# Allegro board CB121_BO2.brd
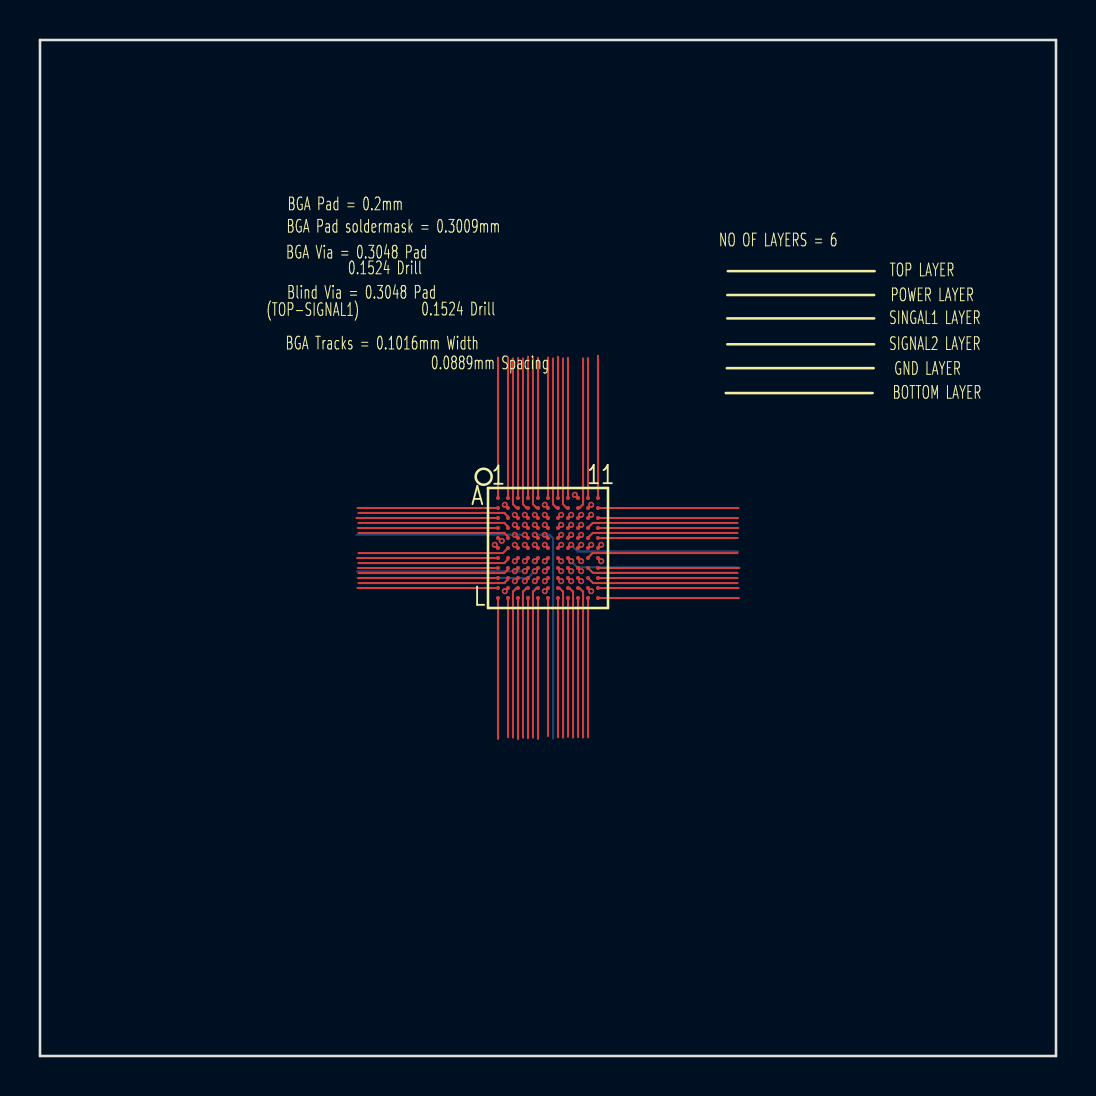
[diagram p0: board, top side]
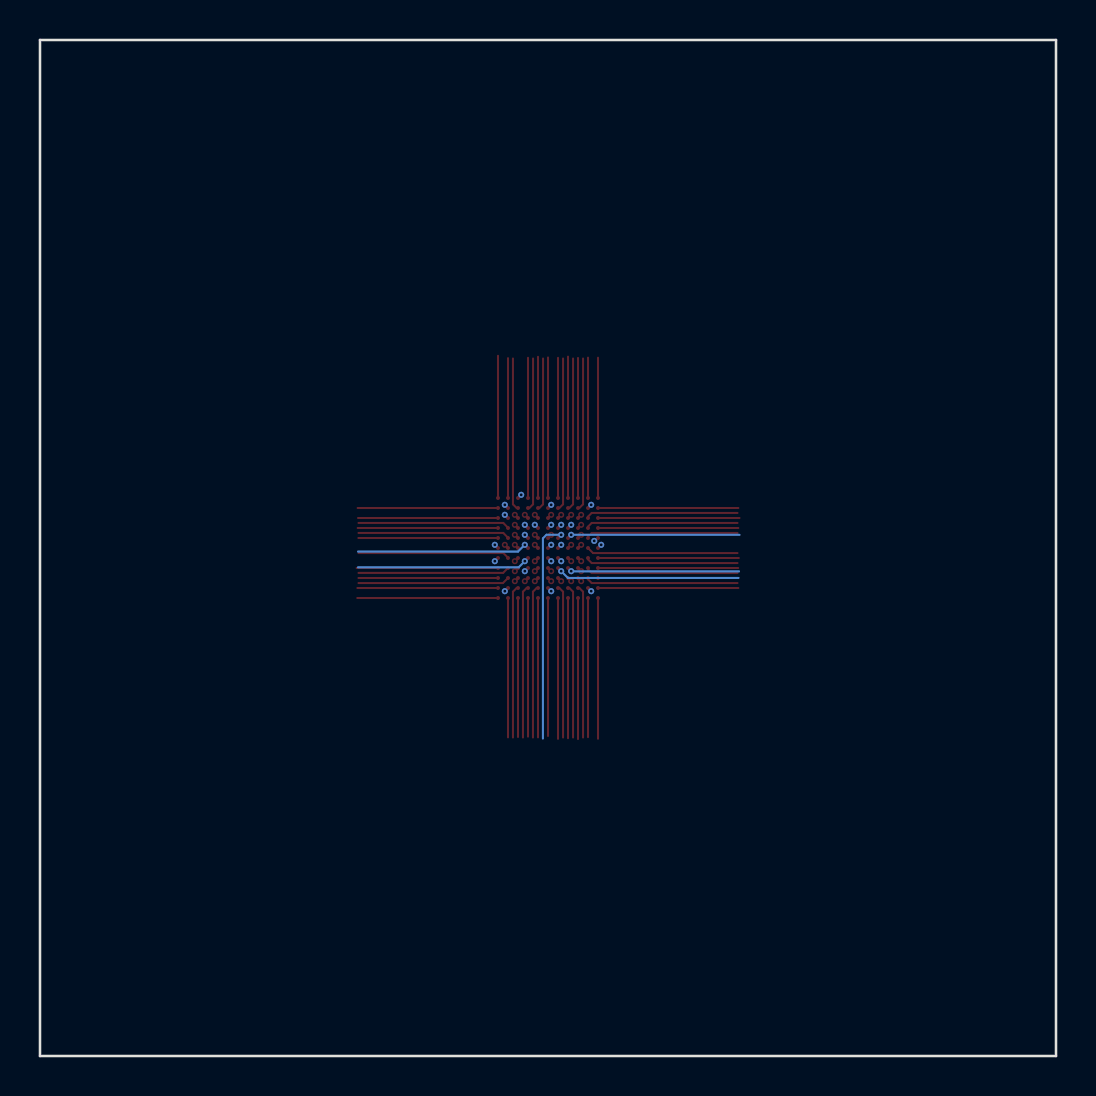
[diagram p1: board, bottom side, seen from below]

Outline 50.8 x 50.8 mm; copper layers: TOP, POWER, SIGNAL1, SIGNAL2, GND, BOTTOM. Coordinates in mm from the lower left corner of the outline.
Outline path: 0,50.8 0,0 50.8,0 50.8,50.8 0,50.8

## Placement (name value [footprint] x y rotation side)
U1  -  [BGA11X11-121_0-2MM]  25.4 25.4 0 top

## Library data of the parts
U1 = BGA11X11-121_0-2MM

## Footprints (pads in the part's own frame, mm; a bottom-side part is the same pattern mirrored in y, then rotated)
BGA11X11-121_0-2MM
  round 0.2 smd: A1(-2.5,2.5) A2(-2,2.5) A3(-1.5,2.5) A4(-1,2.5) A5(-0.5,2.5) A6(0,2.5) A7(0.5,2.5) A8(1,2.5) A9(1.5,2.5) A10(2,2.5) A11(2.5,2.5) B1(-2.5,2) B2(-2,2) B3(-1.5,2) B4(-1,2) B5(-0.5,2) B6(0,2) B7(0.5,2) B8(1,2) B9(1.5,2) B10(2,2) B11(2.5,2) C1(-2.5,1.5) C2(-2,1.5) C3(-1.5,1.5) C4(-1,1.5) C5(-0.5,1.5) C6(0,1.5) C7(0.5,1.5) C8(1,1.5) C9(1.5,1.5) C10(2,1.5) C11(2.5,1.5) D1(-2.5,1) D2(-2,1) D3(-1.5,1) D4(-1,1) D5(-0.5,1) D6(0,1) D7(0.5,1) D8(1,1) D9(1.5,1) D10(2,1) D11(2.5,1) E1(-2.5,0.5) E2(-2,0.5) E3(-1.5,0.5) E4(-1,0.5) E5(-0.5,0.5) E6(0,0.5) E7(0.5,0.5) E8(1,0.5) E9(1.5,0.5) E10(2,0.5) E11(2.5,0.5) F1(-2.5,0) F2(-2,0) F3(-1.5,0) F4(-1,0) F5(-0.5,0) F6(0,0) F7(0.5,0) F8(1,0) F9(1.5,0) F10(2,0) F11(2.5,0) G1(-2.5,-0.5) G2(-2,-0.5) G3(-1.5,-0.5) G4(-1,-0.5) G5(-0.5,-0.5) G6(0,-0.5) G7(0.5,-0.5) G8(1,-0.5) G9(1.5,-0.5) G10(2,-0.5) G11(2.5,-0.5) H1(-2.5,-1) H2(-2,-1) H3(-1.5,-1) H4(-1,-1) H5(-0.5,-1) H6(0,-1) H7(0.5,-1) H8(1,-1) H9(1.5,-1) H10(2,-1) H11(2.5,-1) J1(-2.5,-1.5) J2(-2,-1.5) J3(-1.5,-1.5) J4(-1,-1.5) J5(-0.5,-1.5) J6(0,-1.5) J7(0.5,-1.5) J8(1,-1.5) J9(1.5,-1.5) J10(2,-1.5) J11(2.5,-1.5) K1(-2.5,-2) K2(-2,-2) K3(-1.5,-2) K4(-1,-2) K5(-0.5,-2) K6(0,-2) K7(0.5,-2) K8(1,-2) K9(1.5,-2) K10(2,-2) K11(2.5,-2) L1(-2.5,-2.5) L2(-2,-2.5) L3(-1.5,-2.5) L4(-1,-2.5) L5(-0.5,-2.5) L6(0,-2.5) L7(0.5,-2.5) L8(1,-2.5) L9(1.5,-2.5) L10(2,-2.5) L11(2.5,-2.5)

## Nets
GND: U1.B2 U1.B10 U1.E1 U1.F5 U1.F6 U1.G5 U1.G6 U1.G11 U1.K2 U1.K10
VCC: U1.B6 U1.F1 U1.F11 U1.K6
A1: U1.A1
A2: U1.A2
A3: U1.A3
A4: U1.A4
A5: U1.A5
A6: U1.A6
A7: U1.A7
A8: U1.A8
A10: U1.A10
A11: U1.A11
B1: U1.B1
B3: U1.B3
B4: U1.B4
B5: U1.B5
B7: U1.B7
B8: U1.B8
B9: U1.B9
B11: U1.B11
C1: U1.C1
C2: U1.C2
C3: U1.C3
C4: U1.C4
C5: U1.C5
C6: U1.C6
C7: U1.C7
C8: U1.C8
C9: U1.C9
C11: U1.C11
D1: U1.D1
D2: U1.D2
D3: U1.D3
D4: U1.D4
D5: U1.D5
D6: U1.D6
D7: U1.D7
D8: U1.D8
D9: U1.D9
D10: U1.D10
D11: U1.D11
E2: U1.E2
E3: U1.E3
E4: U1.E4
E5: U1.E5
E6: U1.E6
E7: U1.E7
E8: U1.E8
E9: U1.E9
E10: U1.E10
E11: U1.E11
F2: U1.F2
F3: U1.F3
F4: U1.F4
F7: U1.F7
F8: U1.F8
F9: U1.F9
F10: U1.F10
G1: U1.G1
G2: U1.G2
G3: U1.G3
G4: U1.G4
G7: U1.G7
G8: U1.G8
G9: U1.G9
G10: U1.G10
H1: U1.H1
H2: U1.H2
H3: U1.H3
H4: U1.H4
H5: U1.H5
H6: U1.H6
H7: U1.H7
H8: U1.H8
H9: U1.H9
H10: U1.H10
H11: U1.H11
J1: U1.J1
J2: U1.J2
J3: U1.J3
J4: U1.J4
J5: U1.J5
J6: U1.J6
J7: U1.J7
J8: U1.J8
J9: U1.J9
J10: U1.J10
J11: U1.J11
K1: U1.K1
K3: U1.K3
K4: U1.K4
K5: U1.K5
K7: U1.K7
K8: U1.K8
K9: U1.K9
K11: U1.K11
L1: U1.L1
L2: U1.L2
L3: U1.L3
L4: U1.L4
L5: U1.L5
L6: U1.L6
L7: U1.L7
L8: U1.L8
L9: U1.L9
L10: U1.L10
L11: U1.L11
VPP_2V5: U1.C10
VPP_FAST: U1.A9

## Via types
v1: diameter 0.305, hole 0.152, TOP to SIGNAL1, 33 vias
v2: diameter 0.305, hole 0.152, TOP to BOTTOM, 29 vias

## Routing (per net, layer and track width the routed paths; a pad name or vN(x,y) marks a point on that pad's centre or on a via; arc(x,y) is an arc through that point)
GND: length 2.3
  TOP w0.102: v2(25.24,25.56) U1.F6 ; v2(27.56,23.24) U1.K10 ; U1.E1 23.04,25.76 v2(23.09,25.76) ; v2(24.74,24.74) U1.G5 ; v2(25.24,24.74) U1.G6 ; v2(23.24,23.24) U1.K2 ; v2(28.06,24.74) U1.G11 ; v2(23.24,27.56) U1.B2 ; v2(27.56,27.56) U1.B10 ; v2(24.74,25.56) U1.F5
VCC: length 0.9
  TOP w0.102: v2(28.06,25.56) U1.F11 ; v2(25.24,23.24) U1.K6 ; v2(22.74,25.56) U1.F1 ; v2(25.24,27.56) U1.B6
A1: length 7
  TOP w0.102: U1.A1 22.9,34.91
A2: length 7
  TOP w0.102: U1.A2 23.4,34.92
A3: length 7
  TOP w0.102: U1.A3 23.9,34.9
A4: length 7.1
  TOP w0.102: U1.A4 24.4,34.97
A5: length 7
  TOP w0.102: U1.A5 24.9,34.91
A6: length 7
  TOP w0.102: U1.A6 25.4,34.92
A7: length 7.1
  TOP w0.102: U1.A7 25.9,34.96
A8: length 7
  TOP w0.102: U1.A8 26.4,34.91
A10: length 7
  TOP w0.102: U1.A10 27.4,34.89
A11: length 7.1
  TOP w0.102: U1.A11 27.9,35.01
B1: length 7
  TOP w0.102: U1.B1 15.88,27.4
B3: length 7.6
  TOP w0.102: 23.65,34.87 23.65,27.58 23.83,27.4 U1.B3
B4: length 7.6
  TOP w0.102: U1.B4 24.33,27.4 24.15,27.58 24.15,34.87
B5: length 7.6
  TOP w0.102: U1.B5 24.83,27.4 24.65,27.58 24.65,34.87
B7: length 7.6
  TOP w0.102: U1.B7 25.83,27.4 25.65,27.58 25.65,34.87
B8: length 7.6
  TOP w0.102: U1.B8 26.33,27.4 26.15,27.58 26.15,34.87
B9: length 7.6
  TOP w0.102: 27.15,34.87 27.15,27.58 26.97,27.4 U1.B9
B11: length 7
  TOP w0.102: U1.B11 34.92,27.4
C1: length 7.1
  TOP w0.102: U1.C1 15.83,26.9
C2: length 7.6
  TOP w0.102: U1.C2 23.4,26.97 23.22,27.15 15.93,27.15
C3: length 8.1
  TOP w0.102: v1(23.74,27.06) U1.C3
  SIGNAL1 w0.102: v1(23.74,27.06) 23.74,34.92
C4: length 8
  TOP w0.102: v1(24.24,27.06) U1.C4
  SIGNAL1 w0.102: v1(24.24,27.06) 24.24,34.88
C5: length 8.1
  TOP w0.102: v1(24.74,27.06) U1.C5
  SIGNAL1 w0.102: v1(24.74,27.06) 24.74,34.92
C6: length 8.2
  TOP w0.102: v1(25.24,27.06) U1.C6
  SIGNAL1 w0.102: 24.94,34.92 24.94,27.36 v1(25.24,27.06)
C7: length 8.1
  TOP w0.102: v1(26.06,27.06) U1.C7
  SIGNAL1 w0.102: v1(26.06,27.06) 26.06,34.92
C8: length 8.2
  TOP w0.102: v1(26.56,27.06) U1.C8
  SIGNAL1 w0.102: v1(26.56,27.06) 26.39,27.23 26.39,34.92
C9: length 8.1
  TOP w0.102: v1(27.06,27.06) U1.C9
  SIGNAL1 w0.102: v1(27.06,27.06) 27.06,34.92
C11: length 7
  TOP w0.102: U1.C11 34.9,26.9
D1: length 7
  TOP w0.102: U1.D1 15.88,26.4
D2: length 7.6
  TOP w0.102: 15.93,26.65 23.22,26.65 23.4,26.47 U1.D2
D3: length 8.2
  TOP w0.102: v1(23.74,26.56) U1.D3
  SIGNAL1 w0.102: 15.88,26.9 23.4,26.9 v1(23.74,26.56)
D4: length 8.6
  TOP w0.102: v2(24.24,26.56) U1.D4
  SIGNAL2 w0.102: v2(24.24,26.56) 24.24,34.92
D5: length 8.6
  TOP w0.102: v2(24.74,26.56) U1.D5
  SIGNAL2 w0.102: v2(24.74,26.56) 24.74,34.93
D6: length 8.7
  TOP w0.102: v2(25.24,26.56) U1.D6
  SIGNAL2 w0.102: v2(25.24,26.56) 25.55,26.87 25.55,34.94
D7: length 8.8
  TOP w0.102: v2(26.06,26.56) U1.D7
  SIGNAL2 w0.102: 25.76,34.92 25.76,26.75 25.94,26.56 v2(26.06,26.56)
D8: length 8.6
  TOP w0.102: v2(26.56,26.56) U1.D8
  SIGNAL2 w0.102: v2(26.56,26.56) 34.93,26.56
D9: length 8.1
  TOP w0.102: v1(27.06,26.56) U1.D9
  SIGNAL1 w0.102: v1(27.06,26.56) 34.92,26.56
D10: length 7.6
  TOP w0.102: U1.D10 27.4,26.42 27.64,26.65 34.87,26.65
D11: length 7
  TOP w0.102: U1.D11 34.92,26.4
E2: length 7.6
  TOP w0.102: 15.93,26.15 23.22,26.15 23.4,25.97 U1.E2
E3: length 8.3
  TOP w0.102: v1(23.74,26.06) U1.E3
  SIGNAL1 w0.102: 15.88,26.59 23.21,26.59 v1(23.74,26.06)
E4: length 8.6
  TOP w0.102: v2(24.24,26.06) U1.E4
  BOTTOM w0.102: v2(24.24,26.06) 15.83,26.06
E5: length 11.2
  TOP w0.102: v2(24.74,26.06) U1.E5
  BOTTOM w0.102: v2(24.74,26.06) 25.48,26.06 25.65,25.88 25.65,15.87
E6: length 9.3
  TOP w0.102: v1(25.24,26.06) U1.E6
  SIGNAL1 w0.102: v1(25.24,26.06) 25.37,26.06 25.55,26.24 25.55,34.9
E7: length 9.2
  TOP w0.102: v1(26.06,26.06) U1.E7
  SIGNAL1 w0.102: v1(26.06,26.06) 25.96,26.06 25.76,26.26 25.76,34.9
E8: length 8.6
  TOP w0.102: v2(26.56,26.06) U1.E8
  SIGNAL2 w0.102: v2(26.56,26.06) 34.9,26.06
E9: length 8.2
  TOP w0.102: v1(27.06,26.06) U1.E9
  SIGNAL1 w0.102: v1(27.06,26.06) 27.34,26.34 34.92,26.34
E10: length 7.6
  TOP w0.102: U1.E10 27.4,25.92 27.64,26.15 34.87,26.15
E11: length 7
  TOP w0.102: U1.E11 34.88,25.9
F2: length 7.6
  TOP w0.102: U1.F2 23.15,25.15 15.93,25.15
F3: length 8.4
  TOP w0.102: v1(23.74,25.56) U1.F3
  SIGNAL1 w0.102: v1(23.74,25.56) 23.04,26.26 15.88,26.26
F4: length 8.7
  TOP w0.102: v1(24.24,25.56) U1.F4
  SIGNAL1 w0.102: 15.9,25.25 23.95,25.25 24.24,25.54 v1(24.24,25.56)
F7: length 9.2
  TOP w0.102: v1(26.06,25.56) U1.F7
  SIGNAL1 w0.102: v1(26.06,25.56) 26.06,25.48 26.29,25.25 34.9,25.25
F8: length 8.7
  TOP w0.102: v2(26.56,25.56) U1.F8
  BOTTOM w0.102: v2(26.56,25.56) 26.56,25.56 26.9,25.22 34.9,25.22
F9: length 8.3
  TOP w0.102: v1(27.06,25.56) U1.F9
  SIGNAL1 w0.102: v1(27.06,25.56) 27.64,26.14 34.92,26.14
F10: length 7.7
  TOP w0.102: v1(27.56,25.56) U1.F10
  SIGNAL1 w0.102: 34.92,25.88 27.88,25.88 v1(27.56,25.56)
G1: length 7
  TOP w0.102: U1.G1 15.86,24.9
G2: length 7.6
  TOP w0.102: U1.G2 23.4,24.83 23.22,24.65 15.93,24.65
G3: length 8.1
  TOP w0.102: v1(23.74,24.74) U1.G3
  SIGNAL1 w0.102: v1(23.74,24.74) 15.88,24.74
G4: length 8.7
  TOP w0.102: v1(24.24,24.74) U1.G4
  SIGNAL1 w0.102: v1(24.24,24.74) 24.2,24.74 23.9,25.04 15.87,25.04
G7: length 9.2
  TOP w0.102: v1(26.06,24.74) U1.G7
  SIGNAL1 w0.102: 34.87,25.04 26.34,25.04 26.06,24.76 v1(26.06,24.74)
G8: length 8.7
  TOP w0.102: v2(26.56,24.74) U1.G8
  BOTTOM w0.102: v2(26.56,24.74) 26.87,24.43 34.9,24.43
G9: length 8.2
  TOP w0.102: v1(27.06,24.74) U1.G9
  SIGNAL1 w0.102: 34.92,24.43 27.37,24.43 v1(27.06,24.74)
G10: length 7.6
  TOP w0.102: U1.G10 27.4,24.92 27.63,25.15 34.87,25.15
H1: length 7
  TOP w0.102: U1.H1 15.89,24.4
H2: length 7.6
  TOP w0.102: U1.H2 23.4,24.33 23.22,24.15 15.93,24.15
H3: length 8.1
  TOP w0.102: v1(23.74,24.24) U1.H3
  SIGNAL1 w0.102: v1(23.74,24.24) 15.88,24.24
H4: length 8.8
  TOP w0.102: v2(24.24,24.24) U1.H4
  BOTTOM w0.102: v2(24.24,24.24) 24.32,24.24 24.31,24.23 15.85,24.23
H5: length 9.2
  TOP w0.102: v2(24.74,24.24) U1.H5
  BOTTOM w0.102: 15.87,23.9 24.4,23.9 v2(24.74,24.24)
H6: length 8.7
  TOP w0.102: v1(25.24,24.24) U1.H6
  SIGNAL1 w0.102: 25.55,15.93 25.55,23.9 25.24,24.21 v1(25.24,24.24)
H7: length 8.7
  TOP w0.102: v1(26.06,24.24) U1.H7
  SIGNAL1 w0.102: v1(26.06,24.24) 26.04,24.24 25.76,23.95 25.76,15.93
H8: length 8.5
  TOP w0.102: v2(26.56,24.24) U1.H8
  SIGNAL2 w0.102: v2(26.56,24.24) 34.88,24.24
H9: length 8.1
  TOP w0.102: v1(27.06,24.24) U1.H9
  SIGNAL1 w0.102: v1(27.06,24.24) 34.92,24.24
H10: length 7.6
  TOP w0.102: U1.H10 27.64,24.16 34.87,24.16
H11: length 7.1
  TOP w0.102: U1.H11 34.97,24.4
J1: length 7
  TOP w0.102: U1.J1 15.92,23.9
J2: length 7.6
  TOP w0.102: 15.93,23.65 23.22,23.65 23.4,23.83 U1.J2
J3: length 8.1
  TOP w0.102: v1(23.74,23.74) U1.J3
  SIGNAL1 w0.102: v1(23.74,23.74) 23.74,15.88
J4: length 8.1
  TOP w0.102: v1(24.24,23.74) U1.J4
  SIGNAL1 w0.102: v1(24.24,23.74) 24.24,15.88
J5: length 8.1
  TOP w0.102: v1(24.74,23.74) U1.J5
  SIGNAL1 w0.102: v1(24.74,23.74) 24.74,15.88
J6: length 8.2
  TOP w0.102: v1(25.24,23.74) U1.J6
  SIGNAL1 w0.102: v1(25.24,23.74) 24.94,23.44 24.94,15.88
J7: length 8.1
  TOP w0.102: v1(26.06,23.74) U1.J7
  SIGNAL1 w0.102: v1(26.06,23.74) 26.06,15.88
J8: length 8.1
  TOP w0.102: v1(26.56,23.74) U1.J8
  SIGNAL1 w0.102: v1(26.56,23.74) 26.56,15.88
J9: length 8.1
  TOP w0.102: v1(27.06,23.74) U1.J9
  SIGNAL1 w0.102: v1(27.06,23.74) 34.92,23.74
J10: length 7.6
  TOP w0.102: U1.J10 27.65,23.65 34.87,23.65
J11: length 7
  TOP w0.102: U1.J11 34.88,23.9
K1: length 7
  TOP w0.102: U1.K1 15.88,23.4
K3: length 7.6
  TOP w0.102: 23.65,15.93 23.65,23.22 23.83,23.4 U1.K3
K4: length 7.6
  TOP w0.102: 24.15,15.93 24.15,23.22 24.33,23.4 U1.K4
K5: length 7.6
  TOP w0.102: 24.65,15.93 24.65,23.22 24.83,23.4 U1.K5
K7: length 7.6
  TOP w0.102: U1.K7 25.97,23.4 26.15,23.22 26.15,15.93
K8: length 7.6
  TOP w0.102: U1.K8 26.47,23.4 26.65,23.22 26.65,15.93
K9: length 7.6
  TOP w0.102: 27.15,15.93 27.15,23.22 26.97,23.4 U1.K9
K11: length 7
  TOP w0.102: U1.K11 34.93,23.4
L1: length 7
  TOP w0.102: U1.L1 22.9,15.86
L2: length 7
  TOP w0.102: U1.L2 23.4,15.94
L3: length 7.1
  TOP w0.102: U1.L3 23.9,15.85
L4: length 7
  TOP w0.102: U1.L4 24.4,15.89
L5: length 7
  TOP w0.102: U1.L5 24.9,15.86
L6: length 6.9
  TOP w0.102: U1.L6 25.4,16
L7: length 7
  TOP w0.102: U1.L7 25.9,15.93
L8: length 6.9
  TOP w0.102: U1.L8 26.4,15.97
L9: length 6.9
  TOP w0.102: U1.L9 26.9,15.95
L10: length 7
  TOP w0.102: U1.L10 27.4,15.93
L11: length 7
  TOP w0.102: U1.L11 34.94,22.9
VPP_2V5: length 0.2
  TOP w0.102: v2(27.56,27.06) U1.C10
VPP_FAST: length 0.2
  TOP w0.102: v2(26.74,28.06) U1.A9

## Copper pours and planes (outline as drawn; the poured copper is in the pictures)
GND on GND: 22.38,28.45 28.42,28.45 28.45,28.42 28.45,22.38 28.42,22.35 22.38,22.35 22.35,22.38 22.35,28.42
VCC on POWER: 22.38,28.45 25.65,28.45 25.65,25.86 25.73,25.78 28.45,25.78 28.45,22.38 28.42,22.35 22.38,22.35 22.35,22.38 22.35,28.42
VPP_2V5 on POWER: 25.73,27.53 28.35,27.53 28.45,27.43 28.45,25.91 25.81,25.91 25.73,25.98
VPP_FAST on POWER: 25.76,28.45 28.37,28.45 28.42,28.4 28.42,27.61 25.76,27.61

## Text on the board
Ref Des/Silkscreen Top: (TOP-SIGNAL1) | BGA Tracks = 0.1016mm Width | BGA Via = 0.3048 Pad | 0.1524 Drill | BGA Pad soldermask = 0.3009mm | Blind Via = 0.3048 Pad | BGA Pad = 0.2mm | 0.0889mm Spacing | NO OF LAYERS = 6 | SINGAL1 LAYER | SIGNAL2 LAYER | TOP LAYER | POWER LAYER | BOTTOM LAYER | GND LAYER
